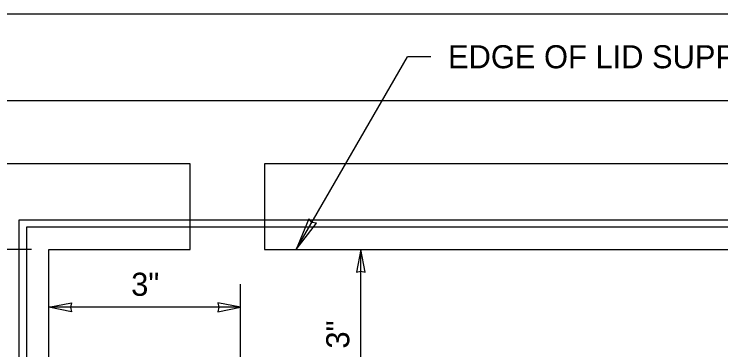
# Model space of a CAD drawing. Extents: x 99862 to 103151, y 100000 to 102076.
# Drawn here: x 101148.1 to 101638.2, y 101842.6 to 102075.5 of the extents above; entities that cross this region are included whole.
import ezdxf

# ---------------------------------------------------------------- set-up
doc = ezdxf.new("R2010")
doc.units = 0
for name, color, linetype in [('Level 1', 7, 'Continuous'), ('Level 15', 7, 'Continuous'), ('Level 2', 7, 'Continuous'), ('Level 20', 7, 'Continuous'), ('Level 3', 7, 'Continuous')]:
    doc.layers.add(name, color=color, linetype=linetype)

msp = doc.modelspace()

# ---------------------------------------------------------------- linework, layer by layer
at = {"layer": 'Level 1'}
msp.add_line((102120.94, 102015.25), (101069.06, 102015.25), dxfattribs=at)
msp.add_lwpolyline([(99862, 99999.5), (103151, 99999.5), (103151, 102075.5), (99862, 102075.5)], close=True, dxfattribs=at)
at = {"layer": 'Level 15'}
for p, q in [((101343.74, 101912.13), (101420.99, 102045.94)), ((101436.99, 102045.94), (101420.99, 102045.94)), ((101160.19, 101912.13), (100983.06, 101912.13)), ((101388.54, 101793.52), (101388.54, 101912.13)), ((101305.14, 101769.47), (101305.14, 101888.08)), ((101305.14, 101872.08), (101172.19, 101872.08))]:
    msp.add_line(p, q, dxfattribs=at)
for points in [[(101343.74, 101912.13), (101357.73, 101930.4), (101354.62, 101930.98), (101352.57, 101933.39)], [(101388.54, 101912.13), (101385.45, 101896.4), (101388.54, 101897.13), (101391.62, 101896.4)], [(101172.19, 101872.08), (101187.91, 101875.16), (101187.18, 101872.08), (101187.91, 101868.99)], [(101305.14, 101872.08), (101289.42, 101875.16), (101290.15, 101872.08), (101289.42, 101868.99)]]:
    msp.add_lwpolyline(points, close=True, dxfattribs=at)
at = {"layer": 'Level 2'}
for p, q in [((101270.16, 101971.52), (101112.79, 101971.52)), ((101270.16, 101912.13), (101270.16, 101971.52)), ((101868.28, 101971.52), (101321.72, 101971.52)), ((101321.72, 101971.52), (101321.72, 101912.13)), ((101172.19, 101597.59), (101172.19, 101912.13)), ((101172.19, 101912.13), (101270.16, 101912.13)), ((101321.72, 101912.13), (101868.28, 101912.13))]:
    msp.add_line(p, q, dxfattribs=at)
at = {"layer": 'Level 3'}
for p, q in [((101151.56, 101932.75), (102038.44, 101932.75)), ((101151.56, 101396.5), (101151.56, 101932.75)), ((102033.28, 101927.59), (101156.72, 101927.59)), ((101156.72, 101927.59), (101156.72, 101401.66))]:
    msp.add_line(p, q, dxfattribs=at)

# ---------------------------------------------------------------- texts
at = {"layer": 'Level 20'}
for s, rotation, p in [('EDGE OF LID SUPPORT FRAME', 360, (101448.99, 102037.94)), ('3"', 90, (101380.54, 101843.46))]:
    msp.add_text(s, height=16, rotation=rotation, dxfattribs=at).set_placement(p)
msp.add_text('3"', height=16, dxfattribs=at).set_placement((101229.3, 101880.08))

doc.saveas('drawing.dxf')
